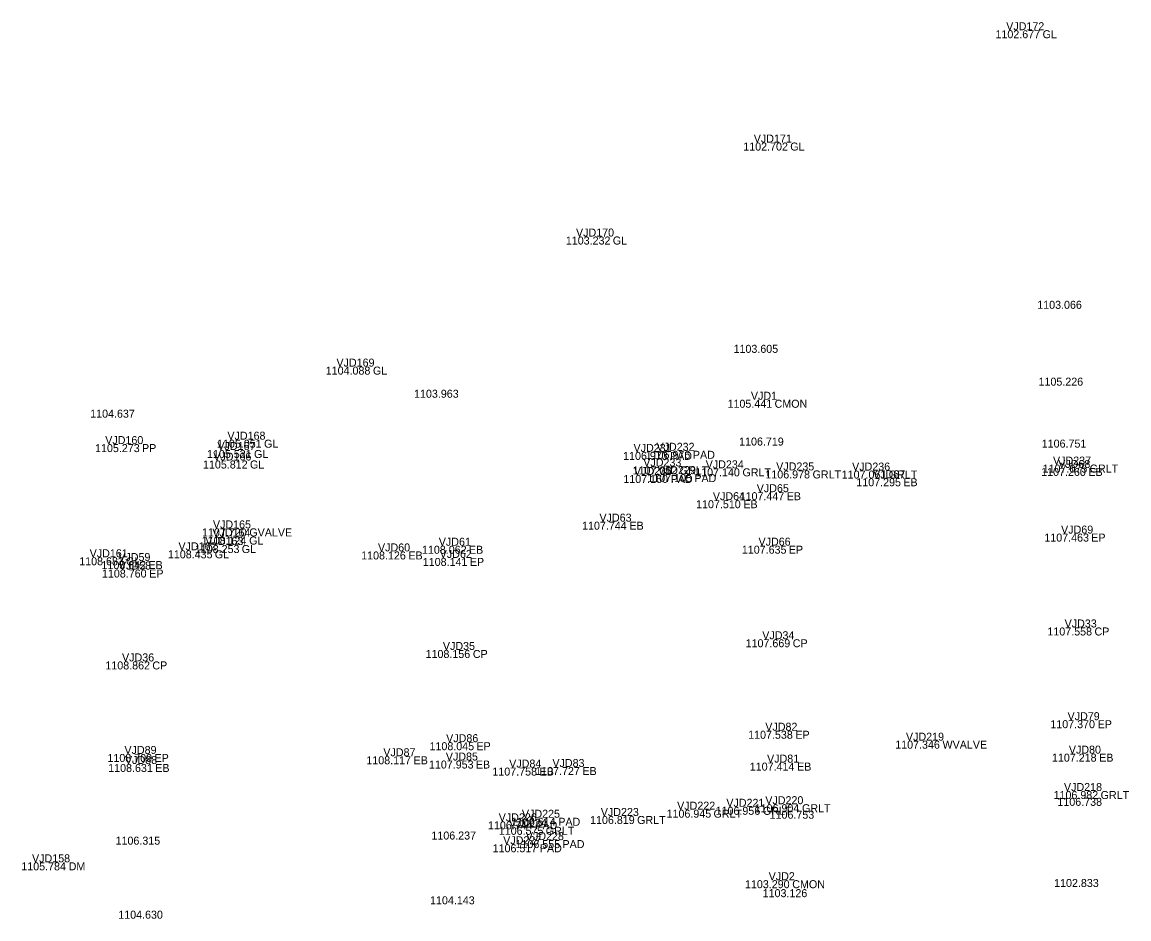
# Model space of a CAD drawing. Extents: x 1629927 to 1630657, y 484405 to 484576.
# Drawn here: x 1630085.6 to 1630223.9, y 484451 to 484563 of the extents above; entities that cross this region are included whole.
import ezdxf

# ---------------------------------------------------------------- set-up
doc = ezdxf.new("R2010")
doc.units = 0
for name, color, linetype in [('SV_X_Text_Comment', 7, 'Continuous'), ('SV_X_Text_Elevation', 7, 'Continuous'), ('SV_X_Text_Name', 7, 'Continuous')]:
    doc.layers.add(name, color=color, linetype=linetype)

msp = doc.modelspace()

# ---------------------------------------------------------------- texts
at = {"layer": 'SV_X_Text_Comment'}
for s, p in [('GL', (1630213.12, 484561.01)), ('GL', (1630181.58, 484546.98)), ('GL', (1630159.4, 484535.24)), ('GL', (1630129.42, 484518.99)), ('CMON', (1630179.62, 484514.85)), ('GL', (1630115.81, 484509.86)), ('PP', (1630100.56, 484509.31)), ('GL', (1630114.56, 484508.57)), ('GL', (1630114.05, 484507.26)), ('PAD', (1630166.55, 484508.34)), ('PAD', (1630169.41, 484508.47)), ('GRLT', (1630167.76, 484506.52)), ('GRLT', (1630175.61, 484506.28)), ('GRLT', (1630184.37, 484506.02)), ('GRLT', (1630193.89, 484506)), ('EB', (1630218.85, 484506.33)), ('GRLT', (1630219, 484506.75)), ('PAD', (1630166.63, 484505.45)), ('PAD', (1630169.59, 484505.56)), ('EB', (1630195.71, 484505.04)), ('EB', (1630181.14, 484503.3)), ('EB', (1630175.72, 484502.3)), ('EB', (1630161.48, 484499.62)), ('GL', (1630113.95, 484497.76)), ('GVALVE', (1630113.97, 484498.78)), ('EP', (1630219.2, 484498.13)), ('GL', (1630109.66, 484496.04)), ('GL', (1630113.02, 484496.7)), ('EB', (1630141.42, 484496.61)), ('EP', (1630181.4, 484496.62)), ('GL', (1630098.57, 484495.17)), ('EB', (1630101.36, 484494.7)), ('EB', (1630133.85, 484495.9)), ('EP', (1630141.53, 484495.09)), ('EP', (1630101.46, 484493.64)), ('CP', (1630219.61, 484486.4)), ('CP', (1630141.91, 484483.59)), ('CP', (1630181.89, 484484.93)), ('CP', (1630101.85, 484482.16)), ('EP', (1630220, 484474.82)), ('EP', (1630182.22, 484473.5)), ('EP', (1630142.36, 484472.07)), ('WVALVE', (1630200.61, 484472.26)), ('EP', (1630102.12, 484470.6)), ('EB', (1630134.5, 484470.31)), ('EB', (1630142.28, 484469.78)), ('EB', (1630220.19, 484470.64)), ('EB', (1630102.21, 484469.35)), ('EB', (1630150.25, 484468.9)), ('EB', (1630155.6, 484468.97)), ('EB', (1630182.44, 484469.52)), ('GRLT', (1630220.37, 484465.97)), ('GRLT', (1630183.05, 484464.32)), ('GRLT', (1630162.44, 484462.85)), ('GRLT', (1630171.99, 484463.64)), ('GRLT', (1630178.16, 484464)), ('PAD', (1630149.72, 484462.18)), ('GRLT', (1630151.02, 484461.5)), ('PAD', (1630152.59, 484462.63)), ('PAD', (1630150.28, 484459.32)), ('PAD', (1630153.11, 484459.84)), ('DM', (1630091.39, 484457.06)), ('CMON', (1630181.83, 484454.83))]:
    msp.add_text(s, height=1, dxfattribs=at).set_placement(p)
at = {"layer": 'SV_X_Text_Elevation'}
for s, p in [('1102.677', (1630207.23, 484561.01)), ('1102.702', (1630175.71, 484546.98)), ('1103.232', (1630153.53, 484535.24)), ('1103.066', (1630212.45, 484527.21)), ('1103.605', (1630174.49, 484521.71)), ('1104.088', (1630123.52, 484518.99)), ('1105.226', (1630212.61, 484517.61)), ('1103.963', (1630134.56, 484516.1)), ('1105.441', (1630173.74, 484514.85)), ('1104.637', (1630094.08, 484513.61)), ('1105.051', (1630109.93, 484509.86)), ('1106.719', (1630175.19, 484510.13)), ('1106.751', (1630213.01, 484509.87)), ('1105.273', (1630094.69, 484509.31)), ('1105.531', (1630108.68, 484508.57)), ('1106.976', (1630163.51, 484508.47)), ('1105.812', (1630108.18, 484507.26)), ('1106.973', (1630160.69, 484508.34)), ('1107.052', (1630161.88, 484506.52)), ('1107.140', (1630169.7, 484506.28)), ('1106.978', (1630178.47, 484506.02)), ('1107.061', (1630188.01, 484506)), ('1107.260', (1630212.94, 484506.33)), ('1107.075', (1630213.13, 484506.75)), ('1107.160', (1630160.72, 484505.45)), ('1107.105', (1630163.72, 484505.56)), ('1107.295', (1630189.84, 484505.04)), ('1107.447', (1630175.25, 484503.3)), ('1107.510', (1630169.81, 484502.3)), ('1107.744', (1630155.56, 484499.62)), ('1108.124', (1630108.03, 484497.76)), ('1107.720', (1630108.06, 484498.78)), ('1107.463', (1630213.34, 484498.13)), ('1108.435', (1630103.79, 484496.04)), ('1108.253', (1630107.16, 484496.7)), ('1108.062', (1630135.55, 484496.61)), ('1107.635', (1630175.53, 484496.62)), ('1108.683', (1630092.71, 484495.17)), ('1108.642', (1630095.49, 484494.7)), ('1108.126', (1630127.95, 484495.9)), ('1108.141', (1630135.65, 484495.09)), ('1108.760', (1630095.55, 484493.64)), ('1107.558', (1630213.72, 484486.4)), ('1108.156', (1630136, 484483.59)), ('1107.669', (1630176, 484484.93)), ('1108.862', (1630095.98, 484482.16)), ('1107.370', (1630214.09, 484474.82)), ('1107.538', (1630176.32, 484473.5)), ('1108.045', (1630136.49, 484472.07)), ('1107.346', (1630194.7, 484472.26)), ('1108.709', (1630096.24, 484470.6)), ('1108.117', (1630128.6, 484470.31)), ('1107.953', (1630136.42, 484469.78)), ('1107.218', (1630214.29, 484470.64)), ('1108.631', (1630096.33, 484469.35)), ('1107.758', (1630144.35, 484468.9)), ('1107.727', (1630149.7, 484468.97)), ('1107.414', (1630176.52, 484469.52)), ('1106.982', (1630214.49, 484465.97)), ('1106.904', (1630177.13, 484464.32)), ('1106.738', (1630214.97, 484465.12)), ('1106.819', (1630156.56, 484462.85)), ('1106.945', (1630166.12, 484463.64)), ('1106.956', (1630172.25, 484464)), ('1106.753', (1630179, 484463.51)), ('1106.744', (1630143.8, 484462.18)), ('1106.575', (1630145.15, 484461.5)), ('1106.614', (1630146.67, 484462.63)), ('1106.315', (1630097.25, 484460.27)), ('1106.237', (1630136.73, 484460.91)), ('1106.517', (1630144.38, 484459.32)), ('1106.555', (1630147.24, 484459.84)), ('1105.784', (1630085.47, 484457.06)), ('1103.290', (1630175.92, 484454.83)), ('1102.833', (1630214.56, 484454.98)), ('1103.126', (1630178.13, 484453.71)), ('1104.143', (1630136.56, 484452.82)), ('1104.630', (1630097.59, 484451.02))]:
    msp.add_text(s, height=1, dxfattribs=at).set_placement(p)
at = {"layer": 'SV_X_Text_Name'}
for s, p in [('VJD172', (1630208.57, 484562.01)), ('VJD171', (1630177.02, 484547.98)), ('VJD170', (1630154.8, 484536.24)), ('VJD169', (1630124.86, 484519.99)), ('VJD1', (1630176.66, 484515.85)), ('VJD160', (1630095.96, 484510.31)), ('VJD168', (1630111.23, 484510.86)), ('VJD167', (1630109.98, 484509.57)), ('VJD231', (1630161.99, 484509.34)), ('VJD232', (1630164.86, 484509.47)), ('VJD166', (1630109.47, 484508.26)), ('VJD233', (1630163.21, 484507.52)), ('VJD234', (1630171.01, 484507.28)), ('VJD237', (1630214.42, 484507.75)), ('VJD68', (1630215.07, 484507.33)), ('VJD230', (1630162.04, 484506.45)), ('VJD229', (1630165.02, 484506.56)), ('VJD235', (1630179.82, 484507.02)), ('VJD236', (1630189.31, 484507)), ('VJD67', (1630191.93, 484506.04)), ('VJD64', (1630171.91, 484503.3)), ('VJD65', (1630177.39, 484504.3)), ('VJD63', (1630157.73, 484500.62)), ('VJD165', (1630109.42, 484499.78)), ('VJD69', (1630215.43, 484499.13)), ('VJD163', (1630108.47, 484497.7)), ('VJD164', (1630109.35, 484498.76)), ('VJD61', (1630137.65, 484497.61)), ('VJD66', (1630177.61, 484497.62)), ('VJD161', (1630094.01, 484496.17)), ('VJD162', (1630105.11, 484497.04)), ('VJD60', (1630130.05, 484496.9)), ('VJD62', (1630137.77, 484496.09)), ('VJD59', (1630097.59, 484495.7)), ('VJD58', (1630097.68, 484494.64)), ('VJD33', (1630215.87, 484487.4)), ('VJD34', (1630178.08, 484485.93)), ('VJD35', (1630138.16, 484484.59)), ('VJD36', (1630098.06, 484483.16)), ('VJD79', (1630216.24, 484475.82)), ('VJD82', (1630178.46, 484474.5)), ('VJD86', (1630138.57, 484473.07)), ('VJD219', (1630196.04, 484473.26)), ('VJD89', (1630098.36, 484471.6)), ('VJD87', (1630130.72, 484471.31)), ('VJD80', (1630216.4, 484471.64)), ('VJD88', (1630098.43, 484470.35)), ('VJD85', (1630138.53, 484470.78)), ('VJD84', (1630146.45, 484469.9)), ('VJD83', (1630151.85, 484469.97)), ('VJD81', (1630178.68, 484470.52)), ('VJD218', (1630215.79, 484466.97)), ('VJD222', (1630167.44, 484464.64)), ('VJD221', (1630173.59, 484465)), ('VJD220', (1630178.46, 484465.32)), ('VJD226', (1630145.14, 484463.18)), ('VJD225', (1630148.04, 484463.63)), ('VJD223', (1630157.9, 484463.85)), ('VJD224', (1630146.41, 484462.5)), ('VJD227', (1630145.7, 484460.32)), ('VJD228', (1630148.53, 484460.84)), ('VJD158', (1630086.81, 484458.06)), ('VJD2', (1630178.88, 484455.83))]:
    msp.add_text(s, height=1, dxfattribs=at).set_placement(p)

doc.saveas('drawing.dxf')
